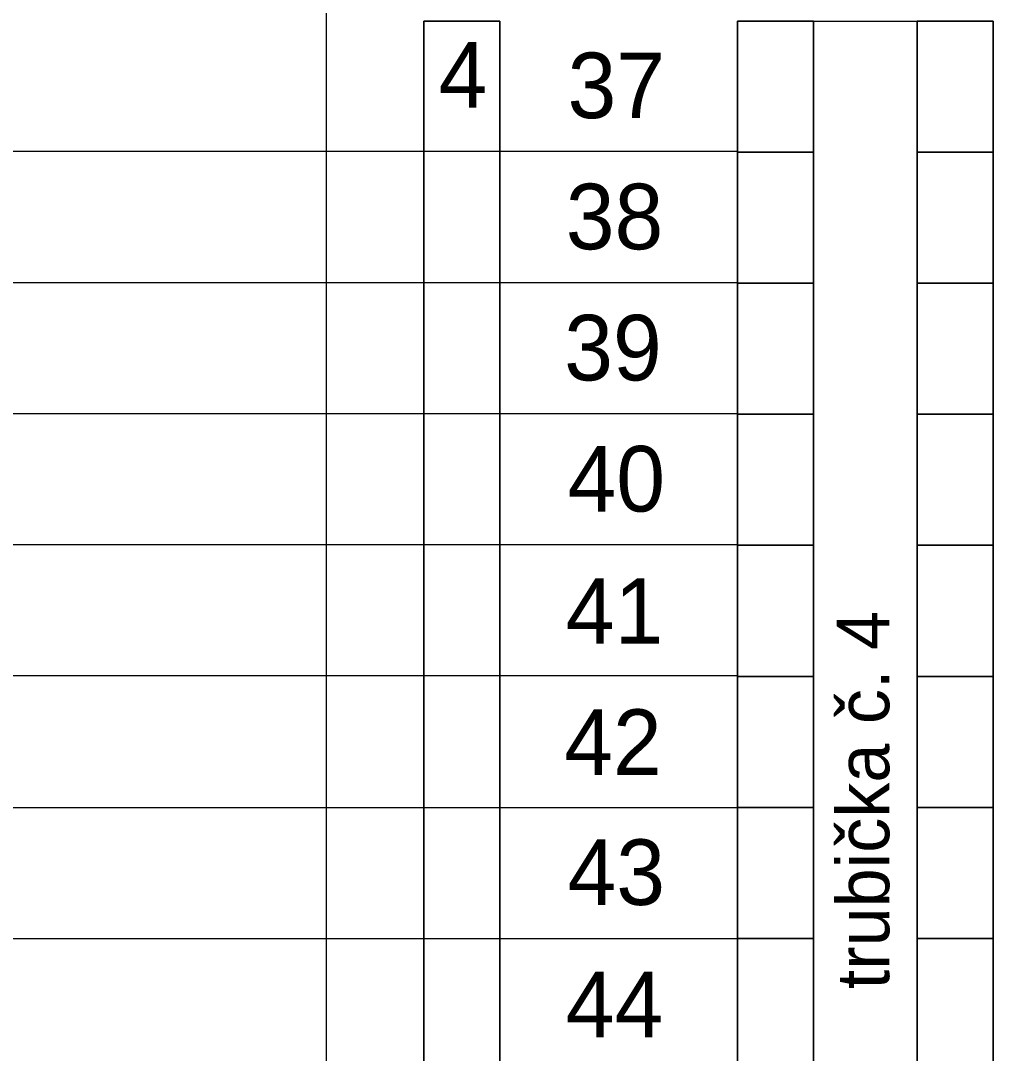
# Model space of a CAD drawing. Extents: x 1901 to 2519, y -3585 to -3154.
# Drawn here: x 2006.66 to 2032.79, y -3357.44 to -3329.72 of the extents above; entities that cross this region are included whole.
import ezdxf

# ---------------------------------------------------------------- set-up
doc = ezdxf.new("R2010")
doc.units = 0
doc.layers.add('rozvláknění', color=7, linetype='Continuous')

msp = doc.modelspace()

# ---------------------------------------------------------------- linework, layer by layer
at = {"layer": 'rozvláknění'}
for p, q in [((1933.193, -3333.223), (2025.898, -3333.225)), ((1933.193, -3336.741), (2025.898, -3336.743)), ((1933.193, -3340.259), (2025.898, -3340.261)), ((1933.193, -3343.777), (2025.898, -3343.779)), ((1933.193, -3347.296), (2025.898, -3347.298)), ((1933.193, -3350.835), (2025.898, -3350.837)), ((1933.193, -3354.354), (2025.898, -3354.356))]:
    msp.add_line(p, q, dxfattribs=at)
for points in [[(2014.869, -3178.545), (2059.522, -3178.544), (2059.522, -3570.656), (2014.869, -3570.656)], [(2019.518, -3371.947), (2017.476, -3371.947), (2017.476, -3329.728), (2019.518, -3329.728)], [(2025.898, -3329.728), (2027.939, -3329.728), (2027.939, -3333.247), (2025.898, -3333.247)], [(2027.939, -3329.728), (2030.726, -3329.728), (2030.726, -3371.943), (2027.939, -3371.943)], [(2030.726, -3329.728), (2032.767, -3329.728), (2032.767, -3333.247), (2030.726, -3333.247)], [(2030.726, -3329.728), (2032.767, -3329.728), (2032.767, -3333.247), (2030.726, -3333.247)], [(2025.898, -3333.247), (2027.939, -3333.247), (2027.939, -3336.765), (2025.898, -3336.765)], [(2030.726, -3333.247), (2032.767, -3333.247), (2032.767, -3336.765), (2030.726, -3336.765)], [(2030.726, -3333.247), (2032.767, -3333.247), (2032.767, -3336.765), (2030.726, -3336.765)], [(2025.898, -3336.765), (2027.939, -3336.765), (2027.939, -3340.283), (2025.898, -3340.283)], [(2030.726, -3336.765), (2032.767, -3336.765), (2032.767, -3340.283), (2030.726, -3340.283)], [(2030.726, -3336.765), (2032.767, -3336.765), (2032.767, -3340.283), (2030.726, -3340.283)], [(2025.898, -3340.283), (2027.939, -3340.283), (2027.939, -3343.801), (2025.898, -3343.801)], [(2030.726, -3340.283), (2032.767, -3340.283), (2032.767, -3343.801), (2030.726, -3343.801)], [(2030.726, -3340.283), (2032.767, -3340.283), (2032.767, -3343.801), (2030.726, -3343.801)], [(2025.898, -3343.801), (2027.939, -3343.801), (2027.939, -3347.319), (2025.898, -3347.319)], [(2030.726, -3343.801), (2032.767, -3343.801), (2032.767, -3347.319), (2030.726, -3347.319)], [(2030.726, -3343.801), (2032.767, -3343.801), (2032.767, -3347.319), (2030.726, -3347.319)], [(2025.898, -3347.319), (2027.939, -3347.319), (2027.939, -3350.837), (2025.898, -3350.837)], [(2030.726, -3347.319), (2032.767, -3347.319), (2032.767, -3350.837), (2030.726, -3350.837)], [(2030.726, -3347.319), (2032.767, -3347.319), (2032.767, -3350.837), (2030.726, -3350.837)], [(2025.898, -3350.837), (2027.939, -3350.837), (2027.939, -3354.356), (2025.898, -3354.356)], [(2030.726, -3350.837), (2032.767, -3350.837), (2032.767, -3354.356), (2030.726, -3354.356)], [(2030.726, -3350.837), (2032.767, -3350.837), (2032.767, -3354.356), (2030.726, -3354.356)], [(2025.898, -3354.356), (2027.939, -3354.356), (2027.939, -3357.874), (2025.898, -3357.874)], [(2030.726, -3354.356), (2032.767, -3354.356), (2032.767, -3357.874), (2030.726, -3357.874)], [(2030.726, -3354.356), (2032.767, -3354.356), (2032.767, -3357.874), (2030.726, -3357.874)]]:
    msp.add_lwpolyline(points, close=True, dxfattribs=at)
for points in [[(2019.518, -3329.728), (2017.476, -3329.728), (2017.476, -3371.947), (2019.518, -3371.947), (2019.518, -3329.728)], [(2019.518, -3329.728), (2017.476, -3329.728), (2017.476, -3371.947), (2019.518, -3371.947), (2019.518, -3329.728)], [(2019.518, -3329.728), (2017.476, -3329.728), (2017.476, -3371.947), (2019.518, -3371.947), (2019.518, -3329.728)], [(2019.518, -3329.728), (2017.476, -3329.728), (2017.476, -3371.947), (2019.518, -3371.947), (2019.518, -3329.728)], [(2019.518, -3329.728), (2017.476, -3329.728), (2017.476, -3371.947), (2019.518, -3371.947), (2019.518, -3329.728)], [(2019.518, -3329.728), (2017.476, -3329.728), (2017.476, -3371.947), (2019.518, -3371.947), (2019.518, -3329.728)], [(2025.898, -3333.247), (2027.939, -3333.247), (2027.939, -3329.728), (2025.898, -3329.728), (2025.898, -3333.247)], [(2025.898, -3333.247), (2027.939, -3333.247), (2027.939, -3329.728), (2025.898, -3329.728), (2025.898, -3333.247)], [(2025.898, -3333.247), (2027.939, -3333.247), (2027.939, -3329.728), (2025.898, -3329.728), (2025.898, -3333.247)], [(2025.898, -3333.247), (2027.939, -3333.247), (2027.939, -3329.728), (2025.898, -3329.728), (2025.898, -3333.247)], [(2025.898, -3333.247), (2027.939, -3333.247), (2027.939, -3329.728), (2025.898, -3329.728), (2025.898, -3333.247)], [(2025.898, -3333.247), (2027.939, -3333.247), (2027.939, -3329.728), (2025.898, -3329.728), (2025.898, -3333.247)], [(2025.898, -3333.247), (2027.939, -3333.247), (2027.939, -3329.728), (2025.898, -3329.728), (2025.898, -3333.247)], [(2025.898, -3333.247), (2027.939, -3333.247), (2027.939, -3329.728), (2025.898, -3329.728), (2025.898, -3333.247)], [(2025.898, -3333.247), (2027.939, -3333.247), (2027.939, -3329.728), (2025.898, -3329.728), (2025.898, -3333.247)], [(2025.898, -3333.247), (2027.939, -3333.247), (2027.939, -3329.728), (2025.898, -3329.728), (2025.898, -3333.247)], [(2030.726, -3333.247), (2032.767, -3333.247), (2032.767, -3329.728), (2030.726, -3329.728), (2030.726, -3333.247)], [(2030.726, -3333.247), (2032.767, -3333.247), (2032.767, -3329.728), (2030.726, -3329.728), (2030.726, -3333.247)], [(2030.726, -3333.247), (2032.767, -3333.247), (2032.767, -3329.728), (2030.726, -3329.728), (2030.726, -3333.247)], [(2030.726, -3333.247), (2032.767, -3333.247), (2032.767, -3329.728), (2030.726, -3329.728), (2030.726, -3333.247)], [(2030.726, -3333.247), (2032.767, -3333.247), (2032.767, -3329.728), (2030.726, -3329.728), (2030.726, -3333.247)], [(2030.726, -3333.247), (2032.767, -3333.247), (2032.767, -3329.728), (2030.726, -3329.728), (2030.726, -3333.247)], [(2030.726, -3333.247), (2032.767, -3333.247), (2032.767, -3329.728), (2030.726, -3329.728), (2030.726, -3333.247)], [(2030.726, -3333.247), (2032.767, -3333.247), (2032.767, -3329.728), (2030.726, -3329.728), (2030.726, -3333.247)], [(2030.726, -3333.247), (2032.767, -3333.247), (2032.767, -3329.728), (2030.726, -3329.728), (2030.726, -3333.247)], [(2030.726, -3333.247), (2032.767, -3333.247), (2032.767, -3329.728), (2030.726, -3329.728), (2030.726, -3333.247)], [(2025.898, -3336.765), (2027.939, -3336.765), (2027.939, -3333.247), (2025.898, -3333.247), (2025.898, -3336.765)], [(2025.898, -3336.765), (2027.939, -3336.765), (2027.939, -3333.247), (2025.898, -3333.247), (2025.898, -3336.765)], [(2025.898, -3336.765), (2027.939, -3336.765), (2027.939, -3333.247), (2025.898, -3333.247), (2025.898, -3336.765)], [(2025.898, -3336.765), (2027.939, -3336.765), (2027.939, -3333.247), (2025.898, -3333.247), (2025.898, -3336.765)], [(2025.898, -3336.765), (2027.939, -3336.765), (2027.939, -3333.247), (2025.898, -3333.247), (2025.898, -3336.765)], [(2025.898, -3336.765), (2027.939, -3336.765), (2027.939, -3333.247), (2025.898, -3333.247), (2025.898, -3336.765)], [(2025.898, -3336.765), (2027.939, -3336.765), (2027.939, -3333.247), (2025.898, -3333.247), (2025.898, -3336.765)], [(2025.898, -3336.765), (2027.939, -3336.765), (2027.939, -3333.247), (2025.898, -3333.247), (2025.898, -3336.765)], [(2025.898, -3336.765), (2027.939, -3336.765), (2027.939, -3333.247), (2025.898, -3333.247), (2025.898, -3336.765)], [(2025.898, -3336.765), (2027.939, -3336.765), (2027.939, -3333.247), (2025.898, -3333.247), (2025.898, -3336.765)], [(2030.726, -3336.765), (2032.767, -3336.765), (2032.767, -3333.247), (2030.726, -3333.247), (2030.726, -3336.765)], [(2030.726, -3336.765), (2032.767, -3336.765), (2032.767, -3333.247), (2030.726, -3333.247), (2030.726, -3336.765)], [(2030.726, -3336.765), (2032.767, -3336.765), (2032.767, -3333.247), (2030.726, -3333.247), (2030.726, -3336.765)], [(2030.726, -3336.765), (2032.767, -3336.765), (2032.767, -3333.247), (2030.726, -3333.247), (2030.726, -3336.765)], [(2030.726, -3336.765), (2032.767, -3336.765), (2032.767, -3333.247), (2030.726, -3333.247), (2030.726, -3336.765)], [(2030.726, -3336.765), (2032.767, -3336.765), (2032.767, -3333.247), (2030.726, -3333.247), (2030.726, -3336.765)], [(2030.726, -3336.765), (2032.767, -3336.765), (2032.767, -3333.247), (2030.726, -3333.247), (2030.726, -3336.765)], [(2030.726, -3336.765), (2032.767, -3336.765), (2032.767, -3333.247), (2030.726, -3333.247), (2030.726, -3336.765)], [(2030.726, -3336.765), (2032.767, -3336.765), (2032.767, -3333.247), (2030.726, -3333.247), (2030.726, -3336.765)], [(2030.726, -3336.765), (2032.767, -3336.765), (2032.767, -3333.247), (2030.726, -3333.247), (2030.726, -3336.765)], [(2025.898, -3340.283), (2027.939, -3340.283), (2027.939, -3336.765), (2025.898, -3336.765), (2025.898, -3340.283)], [(2025.898, -3340.283), (2027.939, -3340.283), (2027.939, -3336.765), (2025.898, -3336.765), (2025.898, -3340.283)], [(2025.898, -3340.283), (2027.939, -3340.283), (2027.939, -3336.765), (2025.898, -3336.765), (2025.898, -3340.283)], [(2025.898, -3340.283), (2027.939, -3340.283), (2027.939, -3336.765), (2025.898, -3336.765), (2025.898, -3340.283)], [(2025.898, -3340.283), (2027.939, -3340.283), (2027.939, -3336.765), (2025.898, -3336.765), (2025.898, -3340.283)], [(2025.898, -3340.283), (2027.939, -3340.283), (2027.939, -3336.765), (2025.898, -3336.765), (2025.898, -3340.283)], [(2025.898, -3340.283), (2027.939, -3340.283), (2027.939, -3336.765), (2025.898, -3336.765), (2025.898, -3340.283)], [(2025.898, -3340.283), (2027.939, -3340.283), (2027.939, -3336.765), (2025.898, -3336.765), (2025.898, -3340.283)], [(2025.898, -3340.283), (2027.939, -3340.283), (2027.939, -3336.765), (2025.898, -3336.765), (2025.898, -3340.283)], [(2025.898, -3340.283), (2027.939, -3340.283), (2027.939, -3336.765), (2025.898, -3336.765), (2025.898, -3340.283)], [(2030.726, -3340.283), (2032.767, -3340.283), (2032.767, -3336.765), (2030.726, -3336.765), (2030.726, -3340.283)], [(2030.726, -3340.283), (2032.767, -3340.283), (2032.767, -3336.765), (2030.726, -3336.765), (2030.726, -3340.283)], [(2030.726, -3340.283), (2032.767, -3340.283), (2032.767, -3336.765), (2030.726, -3336.765), (2030.726, -3340.283)], [(2030.726, -3340.283), (2032.767, -3340.283), (2032.767, -3336.765), (2030.726, -3336.765), (2030.726, -3340.283)], [(2030.726, -3340.283), (2032.767, -3340.283), (2032.767, -3336.765), (2030.726, -3336.765), (2030.726, -3340.283)], [(2030.726, -3340.283), (2032.767, -3340.283), (2032.767, -3336.765), (2030.726, -3336.765), (2030.726, -3340.283)], [(2030.726, -3340.283), (2032.767, -3340.283), (2032.767, -3336.765), (2030.726, -3336.765), (2030.726, -3340.283)], [(2030.726, -3340.283), (2032.767, -3340.283), (2032.767, -3336.765), (2030.726, -3336.765), (2030.726, -3340.283)], [(2030.726, -3340.283), (2032.767, -3340.283), (2032.767, -3336.765), (2030.726, -3336.765), (2030.726, -3340.283)], [(2030.726, -3340.283), (2032.767, -3340.283), (2032.767, -3336.765), (2030.726, -3336.765), (2030.726, -3340.283)], [(2025.898, -3343.801), (2027.939, -3343.801), (2027.939, -3340.283), (2025.898, -3340.283), (2025.898, -3343.801)], [(2025.898, -3343.801), (2027.939, -3343.801), (2027.939, -3340.283), (2025.898, -3340.283), (2025.898, -3343.801)], [(2025.898, -3343.801), (2027.939, -3343.801), (2027.939, -3340.283), (2025.898, -3340.283), (2025.898, -3343.801)], [(2025.898, -3343.801), (2027.939, -3343.801), (2027.939, -3340.283), (2025.898, -3340.283), (2025.898, -3343.801)], [(2025.898, -3343.801), (2027.939, -3343.801), (2027.939, -3340.283), (2025.898, -3340.283), (2025.898, -3343.801)], [(2025.898, -3343.801), (2027.939, -3343.801), (2027.939, -3340.283), (2025.898, -3340.283), (2025.898, -3343.801)], [(2025.898, -3343.801), (2027.939, -3343.801), (2027.939, -3340.283), (2025.898, -3340.283), (2025.898, -3343.801)], [(2025.898, -3343.801), (2027.939, -3343.801), (2027.939, -3340.283), (2025.898, -3340.283), (2025.898, -3343.801)], [(2025.898, -3343.801), (2027.939, -3343.801), (2027.939, -3340.283), (2025.898, -3340.283), (2025.898, -3343.801)], [(2025.898, -3343.801), (2027.939, -3343.801), (2027.939, -3340.283), (2025.898, -3340.283), (2025.898, -3343.801)], [(2030.726, -3343.801), (2032.767, -3343.801), (2032.767, -3340.283), (2030.726, -3340.283), (2030.726, -3343.801)], [(2030.726, -3343.801), (2032.767, -3343.801), (2032.767, -3340.283), (2030.726, -3340.283), (2030.726, -3343.801)], [(2030.726, -3343.801), (2032.767, -3343.801), (2032.767, -3340.283), (2030.726, -3340.283), (2030.726, -3343.801)], [(2030.726, -3343.801), (2032.767, -3343.801), (2032.767, -3340.283), (2030.726, -3340.283), (2030.726, -3343.801)], [(2030.726, -3343.801), (2032.767, -3343.801), (2032.767, -3340.283), (2030.726, -3340.283), (2030.726, -3343.801)], [(2030.726, -3343.801), (2032.767, -3343.801), (2032.767, -3340.283), (2030.726, -3340.283), (2030.726, -3343.801)], [(2030.726, -3343.801), (2032.767, -3343.801), (2032.767, -3340.283), (2030.726, -3340.283), (2030.726, -3343.801)], [(2030.726, -3343.801), (2032.767, -3343.801), (2032.767, -3340.283), (2030.726, -3340.283), (2030.726, -3343.801)], [(2030.726, -3343.801), (2032.767, -3343.801), (2032.767, -3340.283), (2030.726, -3340.283), (2030.726, -3343.801)], [(2030.726, -3343.801), (2032.767, -3343.801), (2032.767, -3340.283), (2030.726, -3340.283), (2030.726, -3343.801)], [(2025.898, -3347.319), (2027.939, -3347.319), (2027.939, -3343.801), (2025.898, -3343.801), (2025.898, -3347.319)], [(2025.898, -3347.319), (2027.939, -3347.319), (2027.939, -3343.801), (2025.898, -3343.801), (2025.898, -3347.319)], [(2025.898, -3347.319), (2027.939, -3347.319), (2027.939, -3343.801), (2025.898, -3343.801), (2025.898, -3347.319)], [(2025.898, -3347.319), (2027.939, -3347.319), (2027.939, -3343.801), (2025.898, -3343.801), (2025.898, -3347.319)], [(2025.898, -3347.319), (2027.939, -3347.319), (2027.939, -3343.801), (2025.898, -3343.801), (2025.898, -3347.319)], [(2025.898, -3347.319), (2027.939, -3347.319), (2027.939, -3343.801), (2025.898, -3343.801), (2025.898, -3347.319)], [(2025.898, -3347.319), (2027.939, -3347.319), (2027.939, -3343.801), (2025.898, -3343.801), (2025.898, -3347.319)], [(2025.898, -3347.319), (2027.939, -3347.319), (2027.939, -3343.801), (2025.898, -3343.801), (2025.898, -3347.319)], [(2025.898, -3347.319), (2027.939, -3347.319), (2027.939, -3343.801), (2025.898, -3343.801), (2025.898, -3347.319)], [(2025.898, -3347.319), (2027.939, -3347.319), (2027.939, -3343.801), (2025.898, -3343.801), (2025.898, -3347.319)], [(2030.726, -3347.319), (2032.767, -3347.319), (2032.767, -3343.801), (2030.726, -3343.801), (2030.726, -3347.319)], [(2030.726, -3347.319), (2032.767, -3347.319), (2032.767, -3343.801), (2030.726, -3343.801), (2030.726, -3347.319)], [(2030.726, -3347.319), (2032.767, -3347.319), (2032.767, -3343.801), (2030.726, -3343.801), (2030.726, -3347.319)], [(2030.726, -3347.319), (2032.767, -3347.319), (2032.767, -3343.801), (2030.726, -3343.801), (2030.726, -3347.319)], [(2030.726, -3347.319), (2032.767, -3347.319), (2032.767, -3343.801), (2030.726, -3343.801), (2030.726, -3347.319)], [(2030.726, -3347.319), (2032.767, -3347.319), (2032.767, -3343.801), (2030.726, -3343.801), (2030.726, -3347.319)], [(2030.726, -3347.319), (2032.767, -3347.319), (2032.767, -3343.801), (2030.726, -3343.801), (2030.726, -3347.319)], [(2030.726, -3347.319), (2032.767, -3347.319), (2032.767, -3343.801), (2030.726, -3343.801), (2030.726, -3347.319)], [(2030.726, -3347.319), (2032.767, -3347.319), (2032.767, -3343.801), (2030.726, -3343.801), (2030.726, -3347.319)], [(2030.726, -3347.319), (2032.767, -3347.319), (2032.767, -3343.801), (2030.726, -3343.801), (2030.726, -3347.319)], [(2025.898, -3350.837), (2027.939, -3350.837), (2027.939, -3347.319), (2025.898, -3347.319), (2025.898, -3350.837)], [(2025.898, -3350.837), (2027.939, -3350.837), (2027.939, -3347.319), (2025.898, -3347.319), (2025.898, -3350.837)], [(2025.898, -3350.837), (2027.939, -3350.837), (2027.939, -3347.319), (2025.898, -3347.319), (2025.898, -3350.837)], [(2025.898, -3350.837), (2027.939, -3350.837), (2027.939, -3347.319), (2025.898, -3347.319), (2025.898, -3350.837)], [(2025.898, -3350.837), (2027.939, -3350.837), (2027.939, -3347.319), (2025.898, -3347.319), (2025.898, -3350.837)], [(2025.898, -3350.837), (2027.939, -3350.837), (2027.939, -3347.319), (2025.898, -3347.319), (2025.898, -3350.837)], [(2025.898, -3350.837), (2027.939, -3350.837), (2027.939, -3347.319), (2025.898, -3347.319), (2025.898, -3350.837)], [(2025.898, -3350.837), (2027.939, -3350.837), (2027.939, -3347.319), (2025.898, -3347.319), (2025.898, -3350.837)], [(2025.898, -3350.837), (2027.939, -3350.837), (2027.939, -3347.319), (2025.898, -3347.319), (2025.898, -3350.837)], [(2025.898, -3350.837), (2027.939, -3350.837), (2027.939, -3347.319), (2025.898, -3347.319), (2025.898, -3350.837)], [(2030.726, -3350.837), (2032.767, -3350.837), (2032.767, -3347.319), (2030.726, -3347.319), (2030.726, -3350.837)], [(2030.726, -3350.837), (2032.767, -3350.837), (2032.767, -3347.319), (2030.726, -3347.319), (2030.726, -3350.837)], [(2030.726, -3350.837), (2032.767, -3350.837), (2032.767, -3347.319), (2030.726, -3347.319), (2030.726, -3350.837)], [(2030.726, -3350.837), (2032.767, -3350.837), (2032.767, -3347.319), (2030.726, -3347.319), (2030.726, -3350.837)], [(2030.726, -3350.837), (2032.767, -3350.837), (2032.767, -3347.319), (2030.726, -3347.319), (2030.726, -3350.837)], [(2030.726, -3350.837), (2032.767, -3350.837), (2032.767, -3347.319), (2030.726, -3347.319), (2030.726, -3350.837)], [(2030.726, -3350.837), (2032.767, -3350.837), (2032.767, -3347.319), (2030.726, -3347.319), (2030.726, -3350.837)], [(2030.726, -3350.837), (2032.767, -3350.837), (2032.767, -3347.319), (2030.726, -3347.319), (2030.726, -3350.837)], [(2030.726, -3350.837), (2032.767, -3350.837), (2032.767, -3347.319), (2030.726, -3347.319), (2030.726, -3350.837)], [(2030.726, -3350.837), (2032.767, -3350.837), (2032.767, -3347.319), (2030.726, -3347.319), (2030.726, -3350.837)], [(2025.898, -3354.356), (2027.939, -3354.356), (2027.939, -3350.837), (2025.898, -3350.837), (2025.898, -3354.356)], [(2025.898, -3354.356), (2027.939, -3354.356), (2027.939, -3350.837), (2025.898, -3350.837), (2025.898, -3354.356)], [(2025.898, -3354.356), (2027.939, -3354.356), (2027.939, -3350.837), (2025.898, -3350.837), (2025.898, -3354.356)], [(2025.898, -3354.356), (2027.939, -3354.356), (2027.939, -3350.837), (2025.898, -3350.837), (2025.898, -3354.356)], [(2025.898, -3354.356), (2027.939, -3354.356), (2027.939, -3350.837), (2025.898, -3350.837), (2025.898, -3354.356)], [(2025.898, -3354.356), (2027.939, -3354.356), (2027.939, -3350.837), (2025.898, -3350.837), (2025.898, -3354.356)], [(2025.898, -3354.356), (2027.939, -3354.356), (2027.939, -3350.837), (2025.898, -3350.837), (2025.898, -3354.356)], [(2025.898, -3354.356), (2027.939, -3354.356), (2027.939, -3350.837), (2025.898, -3350.837), (2025.898, -3354.356)], [(2025.898, -3354.356), (2027.939, -3354.356), (2027.939, -3350.837), (2025.898, -3350.837), (2025.898, -3354.356)], [(2025.898, -3354.356), (2027.939, -3354.356), (2027.939, -3350.837), (2025.898, -3350.837), (2025.898, -3354.356)], [(2030.726, -3354.356), (2032.767, -3354.356), (2032.767, -3350.837), (2030.726, -3350.837), (2030.726, -3354.356)], [(2030.726, -3354.356), (2032.767, -3354.356), (2032.767, -3350.837), (2030.726, -3350.837), (2030.726, -3354.356)], [(2030.726, -3354.356), (2032.767, -3354.356), (2032.767, -3350.837), (2030.726, -3350.837), (2030.726, -3354.356)], [(2030.726, -3354.356), (2032.767, -3354.356), (2032.767, -3350.837), (2030.726, -3350.837), (2030.726, -3354.356)], [(2030.726, -3354.356), (2032.767, -3354.356), (2032.767, -3350.837), (2030.726, -3350.837), (2030.726, -3354.356)], [(2030.726, -3354.356), (2032.767, -3354.356), (2032.767, -3350.837), (2030.726, -3350.837), (2030.726, -3354.356)], [(2030.726, -3354.356), (2032.767, -3354.356), (2032.767, -3350.837), (2030.726, -3350.837), (2030.726, -3354.356)], [(2030.726, -3354.356), (2032.767, -3354.356), (2032.767, -3350.837), (2030.726, -3350.837), (2030.726, -3354.356)], [(2030.726, -3354.356), (2032.767, -3354.356), (2032.767, -3350.837), (2030.726, -3350.837), (2030.726, -3354.356)], [(2030.726, -3354.356), (2032.767, -3354.356), (2032.767, -3350.837), (2030.726, -3350.837), (2030.726, -3354.356)], [(2025.898, -3357.874), (2027.939, -3357.874), (2027.939, -3354.356), (2025.898, -3354.356), (2025.898, -3357.874)], [(2025.898, -3357.874), (2027.939, -3357.874), (2027.939, -3354.356), (2025.898, -3354.356), (2025.898, -3357.874)], [(2025.898, -3357.874), (2027.939, -3357.874), (2027.939, -3354.356), (2025.898, -3354.356), (2025.898, -3357.874)], [(2025.898, -3357.874), (2027.939, -3357.874), (2027.939, -3354.356), (2025.898, -3354.356), (2025.898, -3357.874)], [(2025.898, -3357.874), (2027.939, -3357.874), (2027.939, -3354.356), (2025.898, -3354.356), (2025.898, -3357.874)], [(2025.898, -3357.874), (2027.939, -3357.874), (2027.939, -3354.356), (2025.898, -3354.356), (2025.898, -3357.874)], [(2025.898, -3357.874), (2027.939, -3357.874), (2027.939, -3354.356), (2025.898, -3354.356), (2025.898, -3357.874)], [(2025.898, -3357.874), (2027.939, -3357.874), (2027.939, -3354.356), (2025.898, -3354.356), (2025.898, -3357.874)], [(2025.898, -3357.874), (2027.939, -3357.874), (2027.939, -3354.356), (2025.898, -3354.356), (2025.898, -3357.874)], [(2025.898, -3357.874), (2027.939, -3357.874), (2027.939, -3354.356), (2025.898, -3354.356), (2025.898, -3357.874)], [(2030.726, -3357.874), (2032.767, -3357.874), (2032.767, -3354.356), (2030.726, -3354.356), (2030.726, -3357.874)], [(2030.726, -3357.874), (2032.767, -3357.874), (2032.767, -3354.356), (2030.726, -3354.356), (2030.726, -3357.874)], [(2030.726, -3357.874), (2032.767, -3357.874), (2032.767, -3354.356), (2030.726, -3354.356), (2030.726, -3357.874)], [(2030.726, -3357.874), (2032.767, -3357.874), (2032.767, -3354.356), (2030.726, -3354.356), (2030.726, -3357.874)], [(2030.726, -3357.874), (2032.767, -3357.874), (2032.767, -3354.356), (2030.726, -3354.356), (2030.726, -3357.874)], [(2030.726, -3357.874), (2032.767, -3357.874), (2032.767, -3354.356), (2030.726, -3354.356), (2030.726, -3357.874)], [(2030.726, -3357.874), (2032.767, -3357.874), (2032.767, -3354.356), (2030.726, -3354.356), (2030.726, -3357.874)], [(2030.726, -3357.874), (2032.767, -3357.874), (2032.767, -3354.356), (2030.726, -3354.356), (2030.726, -3357.874)], [(2030.726, -3357.874), (2032.767, -3357.874), (2032.767, -3354.356), (2030.726, -3354.356), (2030.726, -3357.874)], [(2030.726, -3357.874), (2032.767, -3357.874), (2032.767, -3354.356), (2030.726, -3354.356), (2030.726, -3357.874)]]:
    msp.add_lwpolyline(points, dxfattribs=at)

# ---------------------------------------------------------------- texts
for s, p in [('4', (2017.875, -3332.054)), ('37', (2021.337, -3332.335)), ('38', (2021.29, -3335.855)), ('39', (2021.248, -3339.375)), ('40', (2021.337, -3342.895)), ('41', (2021.29, -3346.445)), ('42', (2021.248, -3349.965)), ('43', (2021.337, -3353.455)), ('44', (2021.29, -3357.005))]:
    msp.add_text(s, height=1.76, dxfattribs=at).set_placement(p)
msp.add_text('trubička č. 4', height=1.408, rotation=90, dxfattribs=at).set_placement((2029.974, -3355.717))

doc.saveas('drawing.dxf')
